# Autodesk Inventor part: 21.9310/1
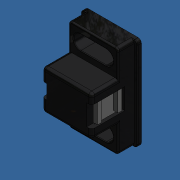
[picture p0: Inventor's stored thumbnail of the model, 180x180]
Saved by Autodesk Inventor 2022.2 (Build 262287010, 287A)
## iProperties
Part Number: 21.9310/1
Material: ABS Plastic
Document SubType Name: Modeling
Designer: amoles
Appearance: Smooth - White
Mass: 2.78438 g
Surface Area: 27.4242 cm^2
Volume: 2.62678 cm^3
Density: 1.06 g/cm^3
Description: MAGNETIC CATCH 30 SUBCOMPONENT
Stock Number: 21.9310/1 MAGNETIC CATCH 30 SUBCOMPONENT
Author: amoles
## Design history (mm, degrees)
feature "093094-1"
body "Solid1"
